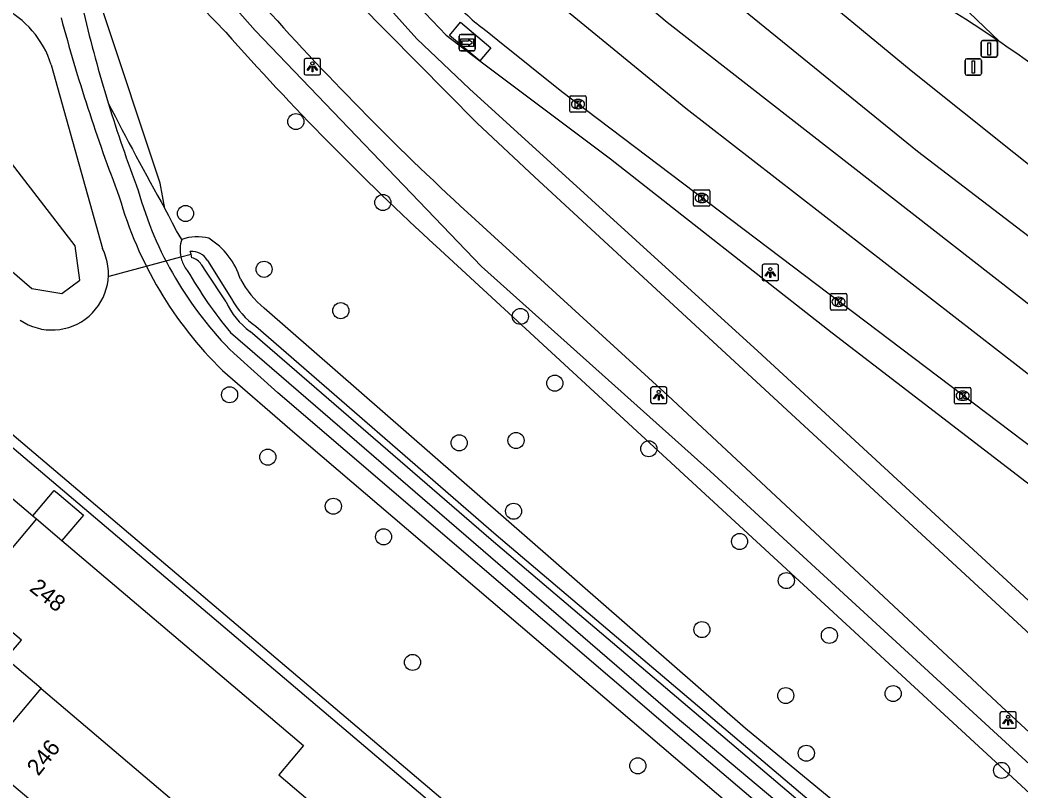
# Model space of a CAD drawing. Extents: x 156414 to 157775, y 382335 to 383765.
# Drawn here: x 157078.1 to 157139, y 382724.7 to 382771.6 of the extents above; entities that cross this region are included whole.
import ezdxf

# ---------------------------------------------------------------- set-up
doc = ezdxf.new("R2010")
doc.units = 0
for name, color, linetype in [('IMGEO_Berm_groen', 7, 'Continuous'), ('IMGEO_Boom', 7, 'Continuous'), ('IMGEO_Duiker', 7, 'Continuous'), ('IMGEO_Fietspad_gesloten', 7, 'Continuous'), ('IMGEO_Groenvoorziening', 7, 'Continuous'), ('IMGEO_Haag', 7, 'Continuous'), ('IMGEO_Kolk', 7, 'Continuous'), ('IMGEO_Lichtpunt', 7, 'Continuous'), ('IMGEO_Meer_plas_ven_vijver', 7, 'Continuous'), ('IMGEO_Pand', 7, 'Continuous'), ('IMGEO_Pand_nummerreeks', 7, 'Continuous'), ('IMGEO_Rijbaan_regionaal_gesloten', 7, 'Continuous'), ('IMGEO_Verkeersbordpaal', 7, 'Continuous'), ('IMGEO_Voetpad_halfverhard', 7, 'Continuous'), ('IMGEO_Waterloop', 7, 'Continuous'), ('IMGEO_Wegwijzer', 7, 'Continuous')]:
    doc.layers.add(name, color=color, linetype=linetype)

msp = doc.modelspace()

# ---------------------------------------------------------------- linework, layer by layer
at = {"layer": 'IMGEO_Berm_groen'}
for points in [[(157171.302, 382706.953), (157123.013, 382751.444), (157105.487, 382767.408), (157102.29, 382770.461), (157093.904, 382779.795), (157087.724, 382788.553), (157092.589, 382783.311), (157099.806, 382775.148), (157104.066, 382770.678), (157106.113, 382769.105)], [(157167.472, 382700.018), (157160.498, 382706.834), (157148.671, 382717.952), (157120.116, 382744.147), (157106.223, 382756.604), (157092.452, 382770.961), (157079.239, 382785.953)], [(157106.113, 382769.105), (157104.258, 382770.664), (157104.928, 382771.462), (157106.783, 382769.903), (157106.113, 382769.105)], [(157106.113, 382769.105), (157114.064, 382763.159), (157127.546, 382752.573), (157144.674, 382739.411), (157156.129, 382731.029), (157165.526, 382723.895), (157174.919, 382717.618), (157179.985, 382713.417), (157186.602, 382702.845), (157190.209, 382693.224), (157190.471, 382690.402), (157190.517, 382689.902), (157190.931, 382685.451), (157190.977, 382684.951), (157191.325, 382681.198), (157190.295, 382670.03), (157187.976, 382664.533), (157185.551, 382661.148), (157174.841, 382648.006), (157162.204, 382633.323)]]:
    msp.add_lwpolyline(points, dxfattribs=at)
at = {"layer": 'IMGEO_Boom'}
for centre in [(157094.924, 382765.417), (157100.215, 382760.493), (157088.213, 382759.823), (157092.992, 382756.428), (157097.657, 382753.912), (157108.578, 382753.562), (157110.672, 382749.499), (157090.895, 382748.795), (157108.314, 382746.015), (157104.857, 382745.87), (157116.388, 382745.509), (157093.219, 382745.001), (157097.204, 382742.014), (157108.164, 382741.706), (157100.259, 382740.153), (157121.908, 382739.868), (157124.75, 382737.487), (157119.617, 382734.506), (157127.37, 382734.153), (157102.018, 382732.513), (157124.717, 382730.493), (157131.249, 382730.617), (157125.968, 382726.984), (157115.721, 382726.22), (157137.842, 382725.942)]:
    msp.add_circle(centre, 0.489, dxfattribs=at)
at = {"layer": 'IMGEO_Duiker'}
msp.add_lwpolyline([(157083.566, 382756.015), (157087.933, 382757.181), (157088.548, 382757.345)], dxfattribs=at)
at = {"layer": 'IMGEO_Fietspad_gesloten'}
for points in [[(157178.59, 382691.216), (157177.296, 382694.161), (157175.005, 382698.637), (157172.473, 382702.727), (157170.065, 382705.661), (157167.437, 382708.486), (157165.272, 382710.671), (157159.453, 382715.857), (157109.445, 382762.045), (157105.947, 382765.328), (157098.702, 382772.669), (157096.753, 382774.573), (157095.601, 382775.89), (157088.763, 382783.053), (157078.36, 382792.607)], [(157105.354, 382759.893), (157117.548, 382748.744), (157139.028, 382728.703), (157156.784, 382712.462)]]:
    msp.add_lwpolyline(points, dxfattribs=at)
msp.add_arc((157224.468, 382889.607), 176.108, 221.54867, 227.43949, dxfattribs=at)
at = {"layer": 'IMGEO_Groenvoorziening'}
for points in [[(157086.962, 382760.132), (157086.664, 382761.674), (157083.15, 382772.27), (157081.78, 382779.801), (157083.79, 382777.948), (157090.659, 382770.855)], [(157080.043, 382768.879), (157083.163, 382757.703)], [(157087.981, 382758.249), (157087.669, 382758.779), (157087.43, 382759.228), (157087.194, 382759.679), (157086.962, 382760.132)], [(157103.46, 382757.831), (157154.886, 382710.404)], [(157088.2, 382756.522), (157088.324, 382756.357)], [(157137.764, 382715.652), (157131.985, 382720.469), (157122.276, 382728.482), (157093.005, 382754.056)], [(157090.946, 382752.582), (157117.996, 382729.241), (157140.217, 382710.582)]]:
    msp.add_lwpolyline(points, dxfattribs=at)
for centre, radius, start, end in [((157074.434, 382767.114), 5.88, 17.46322, 63.80919), ((157223.422, 382888.542), 177.416, 221.55518, 227.45534), ((157243.432, 382848.351), 179.626, 207.08688, 209.41465), ((157089.982, 382757.624), 2.096, 162.65271, 192.20057), ((157088.907, 382755.703), 2.709, 74.52306, 109.99155), ((157087.28, 382754.511), 4.47, 17.21137, 58.28224), ((157080.093, 382756.169), 3.432, 235.50977, 26.54744), ((157089.958, 382757.618), 2.072, 192.17449, 211.93709), ((157112.134, 382770.097), 27.49, 209.98721, 219.57812), ((157096.848, 382758.685), 6.016, 208.28714, 230.3022)]:
    msp.add_arc(centre, radius, start, end, dxfattribs=at)
at = {"layer": 'IMGEO_Haag'}
for points in [[(157083.499, 382631.489), (157100.998, 382616.771), (157155.234, 382680.544), (157057.039, 382763.88), (157024.771, 382733.376), (156998.927, 382703.165), (157017.374, 382687.547)], [(157083.884, 382631.949), (157100.928, 382617.614), (157154.388, 382680.475), (157057.061, 382763.075), (157025.206, 382732.962), (157021.009, 382728.308), (156999.775, 382703.233), (157017.757, 382688.01)]]:
    msp.add_lwpolyline(points, dxfattribs=at)
at = {"layer": 'IMGEO_Kolk'}
for p, q in [((157111.582, 382766.056), (157111.582, 382766.908)), ((157111.657, 382766.982), (157112.509, 382766.982)), ((157112.07, 382766.762), (157112.095, 382766.762)), ((157112.583, 382766.908), (157112.583, 382766.056)), ((157112.509, 382765.982), (157111.657, 382765.982)), ((157112.093, 382766.202), (157112.068, 382766.202)), ((157119.101, 382760.339), (157119.101, 382761.191)), ((157119.176, 382761.265), (157120.028, 382761.265)), ((157119.589, 382761.045), (157119.614, 382761.045)), ((157120.102, 382761.191), (157120.102, 382760.339)), ((157119.612, 382760.485), (157119.587, 382760.485)), ((157120.028, 382760.265), (157119.176, 382760.265)), ((157127.504, 382754.95), (157128.356, 382754.95)), ((157127.429, 382754.024), (157127.429, 382754.876)), ((157127.917, 382754.73), (157127.942, 382754.73)), ((157128.43, 382754.876), (157128.43, 382754.024)), ((157128.356, 382753.95), (157127.504, 382753.95)), ((157127.94, 382754.17), (157127.915, 382754.17)), ((157134.977, 382748.312), (157134.977, 382749.164)), ((157135.052, 382749.238), (157135.904, 382749.238)), ((157135.465, 382749.018), (157135.49, 382749.018)), ((157135.978, 382749.164), (157135.978, 382748.312)), ((157135.904, 382748.238), (157135.052, 382748.238)), ((157135.488, 382748.458), (157135.463, 382748.458))]:
    msp.add_line(p, q, dxfattribs=at)
for points in [[(157111.582, 382766.056), (157111.582, 382766.908)], [(157111.657, 382766.982), (157112.509, 382766.982)], [(157111.903, 382766.682), (157112.026, 382766.682), (157112.026, 382766.531), (157112.156, 382766.682), (157112.32, 382766.682), (157112.174, 382766.531), (157112.327, 382766.282), (157112.175, 382766.282), (157112.09, 382766.446), (157112.026, 382766.379), (157112.026, 382766.282), (157111.903, 382766.282), (157111.903, 382766.682)], [(157112.583, 382766.908), (157112.583, 382766.056)], [(157112.509, 382765.982), (157111.657, 382765.982)], [(157119.101, 382760.339), (157119.101, 382761.191)], [(157119.176, 382761.265), (157120.028, 382761.265)], [(157120.102, 382761.191), (157120.102, 382760.339)], [(157119.422, 382760.965), (157119.545, 382760.965), (157119.545, 382760.814), (157119.675, 382760.965), (157119.839, 382760.965), (157119.693, 382760.814), (157119.846, 382760.565), (157119.694, 382760.565), (157119.609, 382760.729), (157119.545, 382760.662), (157119.545, 382760.565), (157119.422, 382760.565), (157119.422, 382760.965)], [(157120.028, 382760.265), (157119.176, 382760.265)], [(157127.504, 382754.95), (157128.356, 382754.95)], [(157127.429, 382754.024), (157127.429, 382754.876)], [(157127.75, 382754.65), (157127.873, 382754.65), (157127.873, 382754.499), (157128.003, 382754.65), (157128.167, 382754.65), (157128.021, 382754.499), (157128.174, 382754.25), (157128.022, 382754.25), (157127.937, 382754.414), (157127.873, 382754.347), (157127.873, 382754.25), (157127.75, 382754.25), (157127.75, 382754.65)], [(157128.43, 382754.876), (157128.43, 382754.024)], [(157128.356, 382753.95), (157127.504, 382753.95)], [(157134.977, 382748.312), (157134.977, 382749.164)], [(157135.052, 382749.238), (157135.904, 382749.238)], [(157135.298, 382748.938), (157135.421, 382748.938), (157135.421, 382748.787), (157135.551, 382748.938), (157135.715, 382748.938), (157135.569, 382748.787), (157135.722, 382748.538), (157135.57, 382748.538), (157135.485, 382748.702), (157135.421, 382748.635), (157135.421, 382748.538), (157135.298, 382748.538), (157135.298, 382748.938)], [(157135.978, 382749.164), (157135.978, 382748.312)], [(157135.904, 382748.238), (157135.052, 382748.238)]]:
    msp.add_lwpolyline(points, dxfattribs=at)
for centre, start, end in [((157111.659, 382766.906), 91.55205, 178.44795), ((157111.659, 382766.906), 91.55205, 178.44795), ((157112.507, 382766.906), 1.55205, 88.44795), ((157112.507, 382766.906), 1.55205, 88.44795), ((157111.659, 382766.058), 181.55205, 268.44795), ((157111.659, 382766.058), 181.55205, 268.44795), ((157112.507, 382766.058), 271.55205, 358.44795), ((157112.507, 382766.058), 271.55205, 358.44795), ((157119.178, 382761.189), 91.55205, 178.44795), ((157119.178, 382761.189), 91.55205, 178.44795), ((157120.026, 382761.189), 1.55205, 88.44795), ((157120.026, 382761.189), 1.55205, 88.44795), ((157119.178, 382760.341), 181.55205, 268.44795), ((157119.178, 382760.341), 181.55205, 268.44795), ((157120.026, 382760.341), 271.55205, 358.44795), ((157120.026, 382760.341), 271.55205, 358.44795), ((157127.506, 382754.874), 91.55205, 178.44795), ((157127.506, 382754.874), 91.55205, 178.44795), ((157128.354, 382754.874), 1.55205, 88.44795), ((157128.354, 382754.874), 1.55205, 88.44795), ((157127.506, 382754.026), 181.55205, 268.44795), ((157127.506, 382754.026), 181.55205, 268.44795), ((157128.354, 382754.026), 271.55205, 358.44795), ((157128.354, 382754.026), 271.55205, 358.44795), ((157135.054, 382749.162), 91.55205, 178.44795), ((157135.054, 382749.162), 91.55205, 178.44795), ((157135.902, 382749.162), 1.55205, 88.44795), ((157135.902, 382749.162), 1.55205, 88.44795), ((157135.054, 382748.314), 181.55205, 268.44795), ((157135.054, 382748.314), 181.55205, 268.44795), ((157135.902, 382748.314), 271.55205, 358.44795), ((157135.902, 382748.314), 271.55205, 358.44795)]:
    msp.add_arc(centre, 0.0765, start, end, dxfattribs=at)
for centre, major_axis, ratio, start_param, end_param in [((157112.069, 382766.482), (-0.387, 0.002), 0.722429, 4.712389, 7.853982), ((157112.094, 382766.482), (-0.39, 0.002), 0.717154, 1.570796, 4.712389), ((157119.588, 382760.765), (-0.387, 0.002), 0.722429, 4.712389, 7.853982), ((157119.613, 382760.765), (-0.39, 0.002), 0.717154, 1.570796, 4.712389), ((157127.916, 382754.45), (-0.387, 0.002), 0.722429, 4.712389, 7.853982), ((157127.941, 382754.45), (-0.39, 0.002), 0.717154, 1.570796, 4.712389), ((157135.464, 382748.738), (-0.387, 0.002), 0.722429, 4.712389, 7.853982), ((157135.489, 382748.738), (-0.39, 0.002), 0.717154, 1.570796, 4.712389)]:
    msp.add_ellipse(centre, major_axis=major_axis, ratio=ratio, start_param=start_param, end_param=end_param, dxfattribs=at)
at = {"layer": 'IMGEO_Lichtpunt'}
for p, q in [((157095.431, 382769.155), (157095.431, 382768.348)), ((157095.431, 382769.155), (157095.431, 382768.348)), ((157096.333, 382769.25), (157095.525, 382769.25)), ((157096.333, 382769.25), (157095.525, 382769.25)), ((157096.427, 382768.348), (157096.427, 382769.155)), ((157096.427, 382768.348), (157096.427, 382769.155)), ((157095.525, 382768.254), (157096.333, 382768.254)), ((157095.525, 382768.254), (157096.333, 382768.254)), ((157123.281, 382756.639), (157123.281, 382755.832)), ((157123.281, 382756.639), (157123.281, 382755.832)), ((157124.183, 382756.734), (157123.375, 382756.734)), ((157124.183, 382756.734), (157123.375, 382756.734)), ((157124.277, 382755.832), (157124.277, 382756.639)), ((157124.277, 382755.832), (157124.277, 382756.639)), ((157123.375, 382755.738), (157124.183, 382755.738)), ((157123.375, 382755.738), (157124.183, 382755.738)), ((157116.496, 382749.173), (157116.496, 382748.366)), ((157116.496, 382749.173), (157116.496, 382748.366)), ((157117.398, 382749.268), (157116.59, 382749.268)), ((157117.398, 382749.268), (157116.59, 382749.268)), ((157117.492, 382748.366), (157117.492, 382749.173)), ((157117.492, 382748.366), (157117.492, 382749.173)), ((157116.59, 382748.272), (157117.398, 382748.272)), ((157116.59, 382748.272), (157117.398, 382748.272)), ((157137.741, 382729.402), (157137.741, 382728.595)), ((157137.741, 382729.402), (157137.741, 382728.595)), ((157138.643, 382729.497), (157137.835, 382729.497)), ((157138.643, 382729.497), (157137.835, 382729.497)), ((157138.737, 382728.595), (157138.737, 382729.402)), ((157138.737, 382728.595), (157138.737, 382729.402)), ((157137.835, 382728.501), (157138.643, 382728.501)), ((157137.835, 382728.501), (157138.643, 382728.501))]:
    msp.add_line(p, q, dxfattribs=at)
for points in [[(157095.805, 382768.819), (157095.844, 382768.791), (157095.656, 382768.529), (157095.618, 382768.556), (157095.805, 382768.819)], [(157095.907, 382768.771), (157095.954, 382768.771), (157095.954, 382768.449), (157095.907, 382768.449), (157095.907, 382768.771)], [(157096.017, 382768.791), (157096.055, 382768.818), (157096.242, 382768.556), (157096.203, 382768.528), (157096.017, 382768.791)], [(157123.655, 382756.303), (157123.694, 382756.275), (157123.506, 382756.013), (157123.468, 382756.04), (157123.655, 382756.303)], [(157123.757, 382756.255), (157123.804, 382756.255), (157123.804, 382755.933), (157123.757, 382755.933), (157123.757, 382756.255)], [(157123.867, 382756.275), (157123.905, 382756.302), (157124.092, 382756.04), (157124.053, 382756.012), (157123.867, 382756.275)], [(157116.87, 382748.837), (157116.909, 382748.809), (157116.721, 382748.547), (157116.683, 382748.574), (157116.87, 382748.837)], [(157117.082, 382748.809), (157117.12, 382748.836), (157117.307, 382748.574), (157117.268, 382748.546), (157117.082, 382748.809)], [(157116.972, 382748.789), (157117.019, 382748.789), (157117.019, 382748.467), (157116.972, 382748.467), (157116.972, 382748.789)], [(157138.115, 382729.066), (157138.154, 382729.038), (157137.966, 382728.776), (157137.928, 382728.803), (157138.115, 382729.066)], [(157138.217, 382729.018), (157138.264, 382729.018), (157138.264, 382728.696), (157138.217, 382728.696), (157138.217, 382729.018)], [(157138.327, 382729.038), (157138.365, 382729.065), (157138.552, 382728.803), (157138.513, 382728.775), (157138.327, 382729.038)]]:
    msp.add_lwpolyline(points, dxfattribs=at)
for centre in [(157095.93, 382768.953), (157123.78, 382756.437), (157116.995, 382748.971), (157138.24, 382729.2)]:
    msp.add_circle(centre, 0.0994, dxfattribs=at)
for centre, start, end in [((157095.525, 382769.155), 90, 180), ((157095.525, 382769.155), 90, 180), ((157096.333, 382769.155), 0, 90), ((157096.333, 382769.155), 0, 90), ((157095.525, 382768.348), 180, 270), ((157095.525, 382768.348), 180, 270), ((157096.333, 382768.348), 270, 0), ((157096.333, 382768.348), 270, 360), ((157123.375, 382756.639), 90, 180), ((157123.375, 382756.639), 90, 180), ((157124.183, 382756.639), 0, 90), ((157124.183, 382756.639), 0, 90), ((157123.375, 382755.832), 180, 270), ((157123.375, 382755.832), 180, 270), ((157124.183, 382755.832), 270, 0), ((157124.183, 382755.832), 270, 360), ((157116.59, 382749.173), 90, 180), ((157116.59, 382749.173), 90, 180), ((157117.398, 382749.173), 0, 90), ((157117.398, 382749.173), 0, 90), ((157116.59, 382748.366), 180, 270), ((157116.59, 382748.366), 180, 270), ((157117.398, 382748.366), 270, 0), ((157117.398, 382748.366), 270, 360), ((157137.835, 382729.402), 90, 180), ((157137.835, 382729.402), 90, 180), ((157138.643, 382729.402), 0, 90), ((157138.643, 382729.402), 0, 90), ((157137.835, 382728.595), 180, 270), ((157137.835, 382728.595), 180, 270), ((157138.643, 382728.595), 270, 0), ((157138.643, 382728.595), 270, 360)]:
    msp.add_arc(centre, 0.0946, start, end, dxfattribs=at)
at = {"layer": 'IMGEO_Meer_plas_ven_vijver'}
for points in [[(157088.604, 382757.135), (157088.548, 382757.345), (157088.502, 382757.514)], [(157089.545, 382756.968), (157091.018, 382754.641)], [(157090.679, 382754.458), (157089.486, 382756.251), (157089.176, 382756.717)], [(157139.688, 382712.043), (157106.798, 382739.96), (157092.147, 382752.646)], [(157092.498, 382752.965), (157107.116, 382740.281), (157139.991, 382712.383)]]:
    msp.add_lwpolyline(points, dxfattribs=at)
for centre, radius, start, end in [((157088.613, 382756.456), 1.064, 28.77295, 95.96384), ((157088.381, 382756.23), 0.932, 31.50727, 76.17636), ((157094.661, 382756.184), 4.34, 203.42908, 234.59655), ((157095.061, 382756.72), 4.546, 207.2106, 235.68194)]:
    msp.add_arc(centre, radius, start, end, dxfattribs=at)
at = {"layer": 'IMGEO_Pand'}
for points in [[(157054.074, 382752.376), (157053.679, 382752.727), (157056.735, 382756.371), (157060.643, 382753.094), (157062.576, 382755.314), (157078.93, 382741.433)], [(157078.93, 382741.433), (157080.235, 382742.97), (157080.305, 382742.911), (157080.521, 382742.728), (157082.005, 382741.468), (157080.7, 382739.93)], [(157079.156, 382741.241), (157075.139, 382736.476)], [(157078.93, 382741.433), (157079.156, 382741.241)], [(157079.156, 382741.241), (157080.7, 382739.93)], [(157080.7, 382739.93), (157095.395, 382727.457), (157093.881, 382725.663), (157097.016, 382723.022), (157093.58, 382718.937), (157091.818, 382720.395)], [(157079.434, 382730.931), (157077.287, 382732.742), (157078.235, 382733.866), (157075.139, 382736.476)], [(157077.631, 382719.544), (157080.368, 382722.786), (157075.811, 382726.633), (157079.434, 382730.931)], [(157079.434, 382730.931), (157091.818, 382720.395)]]:
    msp.add_lwpolyline(points, dxfattribs=at)
at = {"layer": 'IMGEO_Rijbaan_regionaal_gesloten'}
for points in [[(157137.736, 382770.267), (157131.184, 382776.547), (157092.911, 382809.009)], [(157176.731, 382734.392), (157163.746, 382743.953), (157147.856, 382756.109), (157132.341, 382768.5), (157117.708, 382780.608), (157115.535, 382782.405), (157088.939, 382804.395)], [(157174.847, 382731.771), (157162.999, 382740.45), (157132.735, 382763.592), (157109.286, 382782.662), (157086.519, 382801.732)], [(157172.864, 382729.012), (157151.693, 382744.878), (157142.347, 382752.069), (157117.51, 382771.452), (157084.354, 382799.348)], [(157171.016, 382726.441), (157140.365, 382749.332), (157118.639, 382766.205), (157103.457, 382778.67), (157091.583, 382788.801), (157081.928, 382796.678)], [(157150.413, 382737.149), (157147.425, 382739.454), (157143.782, 382742.375), (157140.605, 382744.878), (157111.102, 382767.229), (157107.208, 382770.343), (157106.877, 382770.604), (157106.549, 382770.868), (157106.224, 382771.135)]]:
    msp.add_lwpolyline(points, dxfattribs=at)
for centre, radius, start, end in [((157085.975, 382694.096), 92.093, 55.80232, 62.03463), ((157131.056, 382801), 38.84, 225.85607, 230.25801), ((157085.901, 382693.942), 92.262, 49.5975, 55.81802)]:
    msp.add_arc(centre, radius, start, end, dxfattribs=at)
at = {"layer": 'IMGEO_Verkeersbordpaal'}
for p, q in [((157136.596, 382769.442), (157136.596, 382770.242)), ((157136.596, 382770.242), (157136.596, 382769.442)), ((157136.696, 382770.342), (157137.486, 382770.342)), ((157137.486, 382770.342), (157136.696, 382770.342)), ((157137.586, 382770.242), (157137.586, 382769.442)), ((157137.586, 382769.442), (157137.586, 382770.242)), ((157135.625, 382768.336), (157135.625, 382769.136)), ((157135.625, 382769.136), (157135.625, 382768.336)), ((157135.725, 382769.236), (157136.515, 382769.236)), ((157136.515, 382769.236), (157135.725, 382769.236)), ((157136.615, 382769.136), (157136.615, 382768.336)), ((157136.615, 382768.336), (157136.615, 382769.136)), ((157137.486, 382769.342), (157136.696, 382769.342)), ((157136.696, 382769.342), (157137.486, 382769.342)), ((157136.515, 382768.236), (157135.725, 382768.236)), ((157135.725, 382768.236), (157136.515, 382768.236))]:
    msp.add_line(p, q, dxfattribs=at)
for points in [[(157137.016, 382770.217), (157137.166, 382770.217), (157137.166, 382769.467), (157137.016, 382769.467), (157137.016, 382770.217)], [(157136.045, 382769.111), (157136.195, 382769.111), (157136.195, 382768.361), (157136.045, 382768.361), (157136.045, 382769.111)]]:
    msp.add_lwpolyline(points, dxfattribs=at)
for centre, start, end in [((157136.696, 382770.242), 90, 180), ((157136.696, 382770.242), 90, 180), ((157137.486, 382770.242), 0, 90), ((157137.486, 382770.242), 360, 90), ((157135.725, 382769.136), 90, 180), ((157135.725, 382769.136), 90, 180), ((157136.515, 382769.136), 0, 90), ((157136.515, 382769.136), 360, 90), ((157136.696, 382769.442), 180, 270), ((157136.696, 382769.442), 180, 270), ((157137.486, 382769.442), 270, 0), ((157137.486, 382769.442), 270, 0), ((157135.725, 382768.336), 180, 270), ((157135.725, 382768.336), 180, 270), ((157136.515, 382768.336), 270, 0), ((157136.515, 382768.336), 270, 0)]:
    msp.add_arc(centre, 0.1, start, end, dxfattribs=at)
at = {"layer": 'IMGEO_Voetpad_halfverhard'}
for points in [[(157141.308, 382708.365), (157118.246, 382727.979), (157093.836, 382748.922), (157091.149, 382751.318)], [(157090.456, 382750.276), (157094.852, 382746.463), (157123.976, 382721.585), (157140.328, 382707.415)]]:
    msp.add_lwpolyline(points, dxfattribs=at)
for centre, radius, start, end in [((157165.072, 382791.584), 85.317, 193.24496, 197.05627), ((157185.469, 382799.816), 108.519, 194.99887, 201.04468), ((157166.185, 382791.939), 86.484, 197.06462, 200.79622), ((157106.91, 382767.222), 22.391, 195.51439, 225.25899), ((157107.159, 382767.324), 23.867, 195.74585, 225.5852)]:
    msp.add_arc(centre, radius, start, end, dxfattribs=at)
at = {"layer": 'IMGEO_Waterloop'}
msp.add_lwpolyline([(156994.491, 382709.359), (156996.189, 382707.831), (157010.245, 382724.136), (157017.039, 382731.652), (157022.177, 382737.512), (157030.075, 382744.688), (157057.124, 382770.209), (157059.077, 382772.332), (157078.865, 382755.262), (157080.691, 382754.964), (157081.795, 382755.771), (157081.497, 382757.852), (157069.183, 382773.86), (157062.984, 382778.361), (157060.011, 382777.512), (157046.933, 382763.499), (157019.417, 382737.937), (157009.565, 382726.981), (156994.491, 382709.359)], dxfattribs=at)
at = {"layer": 'IMGEO_Wegwijzer'}
for p, q in [((157104.848, 382769.82), (157104.848, 382770.62)), ((157104.848, 382770.62), (157104.848, 382769.82)), ((157104.948, 382770.72), (157105.738, 382770.72)), ((157105.738, 382770.72), (157104.948, 382770.72)), ((157105.838, 382770.62), (157105.838, 382769.82)), ((157105.838, 382769.82), (157105.838, 382770.62)), ((157105.738, 382769.72), (157104.948, 382769.72)), ((157104.948, 382769.72), (157105.738, 382769.72))]:
    msp.add_line(p, q, dxfattribs=at)
for points in [[(157104.949, 382770.452), (157105.737, 382770.452), (157105.737, 382769.988), (157104.949, 382769.988), (157104.949, 382770.452)], [(157105.014, 382770.304), (157105.014, 382770.22), (157105.014, 382770.136), (157105.425, 382770.136), (157105.425, 382770.053), (157105.672, 382770.22), (157105.425, 382770.387), (157105.425, 382770.304), (157105.014, 382770.304)]]:
    msp.add_lwpolyline(points, dxfattribs=at)
for centre, start, end in [((157104.948, 382770.62), 90, 180), ((157104.948, 382770.62), 90, 180), ((157105.738, 382770.62), 0, 90), ((157105.738, 382770.62), 360, 90), ((157104.948, 382769.82), 180, 270), ((157104.948, 382769.82), 180, 270), ((157105.738, 382769.82), 270, 0), ((157105.738, 382769.82), 270, 0)]:
    msp.add_arc(centre, 0.1, start, end, dxfattribs=at)

# ---------------------------------------------------------------- texts
at = {"layer": 'IMGEO_Pand_nummerreeks'}
for s, rotation, p in [('248', 321.26232, (157078.662, 382736.919)), ('246', 51.541, (157079.263, 382725.555))]:
    msp.add_text(s, height=1, rotation=rotation, dxfattribs=at).set_placement(p)

doc.saveas('drawing.dxf')
